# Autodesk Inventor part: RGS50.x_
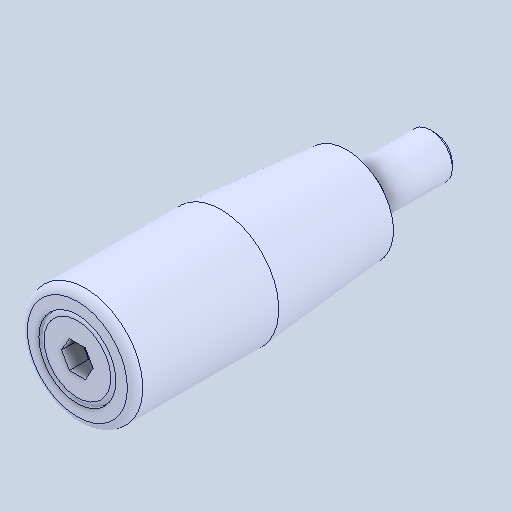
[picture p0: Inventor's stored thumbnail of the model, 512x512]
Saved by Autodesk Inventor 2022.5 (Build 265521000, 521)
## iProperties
Created: 2024-01
Part Number: RGS50.x_
Material: 一般
Document SubType Name: Modeling
Designer: ImaoCorp
Density: 1 g/cm^3
Appearance: 既定
Author: ImaoCorp
Sending System: SOLIDWORKS 2022-2022290
MC: AMD64
MC_MODEL: Intel64 Family 6 Model 60 Stepping 3, GenuineIntel
OS: Windows_NT
FRU: Parasolid Version 33.1, build 260,  4-25-2022
FORMAT: text
GUISE: transmit
KEY: FILERGS50.x_t
DATE: Thu Jan 25 16:25:09 2024
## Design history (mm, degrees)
feature "Base1"
node "ソリッド1"
